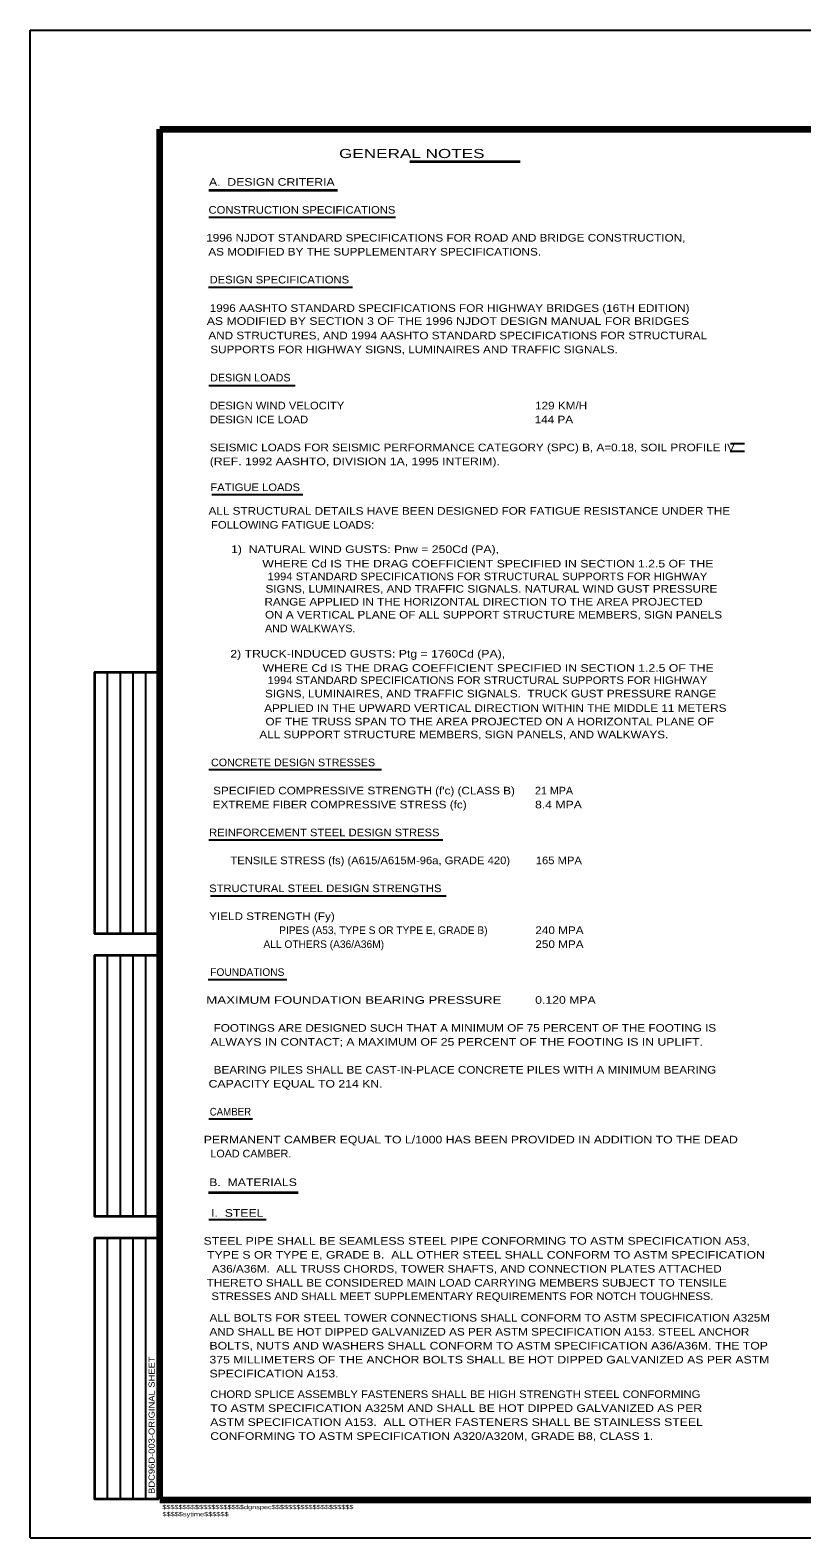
# Model space of a CAD drawing. Extents: x 312601.858 to 312602.699, y 144420.109 to 144420.704.
# Drawn here: x 312601.858 to 312602.162, y 144420.109 to 144420.704 of the extents above; entities that cross this region are included whole.
import ezdxf
from ezdxf.enums import TextEntityAlignment as Align

# ---------------------------------------------------------------- set-up
doc = ezdxf.new("R2010")
doc.units = 0
doc.header["$LTSCALE"] = 0.0012
for name, color, linetype, lineweight in [('2', 7, 'Continuous', 25), ('39', 7, 'Continuous', 25), ('60', 7, 'Continuous', 25)]:
    doc.layers.add(name, color=color, linetype=linetype, lineweight=lineweight)

msp = doc.modelspace()

# ---------------------------------------------------------------- linework, layer by layer
at = {"layer": '2', "lineweight": 35}
for p, q in [((312602.0073, 144420.6518), (312602.0507, 144420.6518)), ((312601.9282, 144420.6405), (312601.9788, 144420.6405)), ((312601.928, 144420.2456), (312601.9633, 144420.2456))]:
    msp.add_line(p, q, dxfattribs=at)
at = {"layer": '2'}
for p, q in [((312601.9282, 144420.6298), (312602.0017, 144420.6298)), ((312601.928, 144420.6023), (312601.9847, 144420.6023)), ((312601.9281, 144420.5635), (312601.9622, 144420.5635)), ((312602.1335, 144420.5406), (312602.139, 144420.5406)), ((312602.1334, 144420.5376), (312602.139, 144420.5376)), ((312601.9293, 144420.5205), (312601.9652, 144420.5205)), ((312601.9282, 144420.4122), (312601.9961, 144420.4122)), ((312601.9282, 144420.3845), (312602.0203, 144420.3845)), ((312601.9288, 144420.3625), (312602.0216, 144420.3625)), ((312601.9279, 144420.3295), (312601.9589, 144420.3295)), ((312601.9281, 144420.2746), (312601.9453, 144420.2746)), ((312601.9281, 144420.2349), (312601.9507, 144420.2349))]:
    msp.add_line(p, q, dxfattribs=at)
at = {"layer": '39'}
for p, q in [((312601.8578, 144420.7035), (312602.6988, 144420.7035)), ((312601.8578, 144420.1095), (312601.8578, 144420.7035)), ((312601.8578, 144420.1095), (312602.6988, 144420.1095))]:
    msp.add_line(p, q, dxfattribs=at)
at = {"layer": '39', "lineweight": 158}
for p, q in [((312601.9088, 144420.6645), (312602.6838, 144420.6645)), ((312601.9088, 144420.1247), (312601.9088, 144420.6645)), ((312601.9088, 144420.1245), (312602.6838, 144420.1245))]:
    msp.add_line(p, q, dxfattribs=at)
at = {"layer": '60'}
for p, q in [((312601.8883, 144420.3475), (312601.8883, 144420.4505)), ((312601.8933, 144420.3475), (312601.8933, 144420.4505)), ((312601.8983, 144420.3475), (312601.8983, 144420.4505)), ((312601.9034, 144420.3475), (312601.9034, 144420.4505)), ((312601.8883, 144420.2361), (312601.8883, 144420.3391)), ((312601.8933, 144420.2361), (312601.8933, 144420.3391)), ((312601.8983, 144420.2361), (312601.8983, 144420.3391)), ((312601.9034, 144420.2361), (312601.9034, 144420.3391)), ((312601.8883, 144420.1247), (312601.8883, 144420.2277)), ((312601.8933, 144420.1247), (312601.8933, 144420.2277)), ((312601.8983, 144420.1247), (312601.8983, 144420.2277)), ((312601.9034, 144420.1247), (312601.9034, 144420.2277))]:
    msp.add_line(p, q, dxfattribs=at)
at = {"layer": '60', "lineweight": 35}
for points in [[(312601.9084, 144420.3475), (312601.8833, 144420.3475), (312601.8833, 144420.4505), (312601.9084, 144420.4505)], [(312601.9084, 144420.2361), (312601.8833, 144420.2361), (312601.8833, 144420.3391), (312601.9084, 144420.3391)], [(312601.9084, 144420.1247), (312601.8833, 144420.1247), (312601.8833, 144420.2277), (312601.9084, 144420.2277)]]:
    msp.add_lwpolyline(points, dxfattribs=at)

# ---------------------------------------------------------------- texts
at = {"layer": '2'}
for s, height, width, p in [('                         GENERAL NOTES', 0.0036, 1.4, (312601.98465, 144420.6531)), ('A.  DESIGN CRITERIA', 0.003, 1.2, (312601.95295, 144420.6422)), ('CONSTRUCTION SPECIFICATIONS', 0.003, 1.1, (312601.9648, 144420.6312)), ('1996 NJDOT STANDARD SPECIFICATIONS FOR ROAD AND BRIDGE CONSTRUCTION,', 0.003, 1.15, (312602.02145, 144420.6202)), ('AS MODIFIED BY THE SUPPLEMENTARY SPECIFICATIONS.', 0.003, 1.15, (312601.99345, 144420.6147)), ('DESIGN SPECIFICATIONS', 0.003, 1.1, (312601.9559, 144420.6037)), ('1996 AASHTO STANDARD SPECIFICATIONS FOR HIGHWAY BRIDGES (16TH EDITION)', 0.003, 1.15, (312602.02295, 144420.5925)), ('AS MODIFIED BY SECTION 3 OF THE 1996 NJDOT DESIGN MANUAL FOR BRIDGES', 0.003, 1.2, (312602.0223, 144420.5874)), ('AND STRUCTURES, AND 1994 AASHTO STANDARD SPECIFICATIONS FOR STRUCTURAL', 0.003, 1.15, (312602.02615, 144420.5817)), ('SUPPORTS FOR HIGHWAY SIGNS, LUMINAIRES AND TRAFFIC SIGNALS.', 0.003, 1.15, (312602.00895, 144420.5762)), ('DESIGN LOADS', 0.003, 1.05, (312601.9445, 144420.5651)), ('129 KM/H', 0.003, 1.15, (312602.06685, 144420.5541)), ('144 PA', 0.003, 1.15, (312602.064, 144420.5486)), ('FATIGUE LOADS', 0.003, 1.1, (312601.9464, 144420.5219)), ('ALL STRUCTURAL DETAILS HAVE BEEN DESIGNED FOR FATIGUE RESISTANCE UNDER THE', 0.003, 1.15, (312602.0307, 144420.5126)), ('FOLLOWING FATIGUE LOADS:', 0.003, 1.1, (312601.96115, 144420.5071)), ('1)  NATURAL WIND GUSTS: Pnw = 250Cd (PA),', 0.003, 1.2, (312601.98965, 144420.4975)), ('WHERE Cd IS THE DRAG COEFFICIENT SPECIFIED IN SECTION 1.2.5 OF THE', 0.003, 1.2, (312602.038, 144420.4918)), ('1994 STANDARD SPECIFICATIONS FOR STRUCTURAL SUPPORTS FOR HIGHWAY', 0.003, 1.1, (312602.03785, 144420.4868)), ('RANGE APPLIED IN THE HORIZONTAL DIRECTION TO THE AREA PROJECTED', 0.003, 1.15, (312602.0363, 144420.4768)), ('SIGNS, LUMINAIRES, AND TRAFFIC SIGNALS. NATURAL WIND GUST PRESSURE', 0.003, 1.15, (312602.0394, 144420.4819)), ('ON A VERTICAL PLANE OF ALL SUPPORT STRUCTURE MEMBERS, SIGN PANELS', 0.003, 1.15, (312602.04025, 144420.4717)), ('AND WALKWAYS.', 0.003, 1.05, (312601.96805, 144420.4663)), ('2) TRUCK-INDUCED GUSTS: Ptg = 1760Cd (PA),', 0.003, 1.2, (312601.9907, 144420.4563)), ('WHERE Cd IS THE DRAG COEFFICIENT SPECIFIED IN SECTION 1.2.5 OF THE', 0.003, 1.2, (312602.0381, 144420.4507)), ('SIGNS, LUMINAIRES, AND TRAFFIC SIGNALS.  TRUCK GUST PRESSURE RANGE', 0.003, 1.15, (312602.0391, 144420.4406)), ('1994 STANDARD SPECIFICATIONS FOR STRUCTURAL SUPPORTS FOR HIGHWAY', 0.003, 1.1, (312602.03785, 144420.4459)), ('APPLIED IN THE UPWARD VERTICAL DIRECTION WITHIN THE MIDDLE 11 METERS', 0.003, 1.15, (312602.04095, 144420.4349)), ('OF THE TRUSS SPAN TO THE AREA PROJECTED ON A HORIZONTAL PLANE OF', 0.003, 1.15, (312602.03875, 144420.4296)), ('ALL SUPPORT STRUCTURE MEMBERS, SIGN PANELS, AND WALKWAYS.', 0.003, 1.15, (312602.02855, 144420.4245)), ('CONCRETE DESIGN STRESSES', 0.003, 1.05, (312601.9613, 144420.4135)), ("SPECIFIED COMPRESSIVE STRENGTH (f'c) (CLASS B)          ", 0.003, 1.15, (312601.99565, 144420.4024)), ('21 MPA', 0.003, 1.05, (312602.06405, 144420.4024)), ('EXTREME FIBER COMPRESSIVE STRESS (fc)             ', 0.003, 1.15, (312601.988, 144420.3969)), ('8.4 MPA', 0.003, 1.2, (312602.0658, 144420.3969)), ('REINFORCEMENT STEEL DESIGN STRESS', 0.003, 1.1, (312601.9736, 144420.3859)), ('TENSILE STRESS (fs) (A615/A615M-96a, GRADE 420)                        ', 0.003, 1.1, (312602.0064, 144420.3749)), ('165 MPA', 0.003, 1.1, (312602.06595, 144420.3749)), ('STRUCTURAL STEEL DESIGN STRENGTHS', 0.003, 1.1, (312601.974, 144420.3639)), ('YIELD STRENGTH (Fy)', 0.003, 1.15, (312601.953, 144420.3529)), ('240 MPA', 0.003, 1.15, (312602.0662, 144420.3474)), ('250 MPA', 0.003, 1.15, (312602.0662, 144420.3419)), ('MAXIMUM FOUNDATION BEARING PRESSURE             ', 0.003, 1.3, (312601.99465, 144420.3199)), ('0.120 MPA', 0.003, 1.2, (312602.06855, 144420.3199)), ('FOOTINGS ARE DESIGNED SUCH THAT A MINIMUM OF 75 PERCENT OF THE FOOTING IS', 0.003, 1.15, (312602.02895, 144420.3089)), ('ALWAYS IN CONTACT; A MAXIMUM OF 25 PERCENT OF THE FOOTING IS IN UPLIFT.', 0.003, 1.2, (312602.02575, 144420.3034)), ('BEARING PILES SHALL BE CAST-IN-PLACE CONCRETE PILES WITH A MINIMUM BEARING', 0.003, 1.15, (312602.029, 144420.2924)), ('CAPACITY EQUAL TO 214 KN.', 0.003, 1.2, (312601.9623, 144420.2869)), ('CAMBER', 0.003, 0.95, (312601.93665, 144420.2759)), ('PERMANENT CAMBER EQUAL TO L/1000 HAS BEEN PROVIDED IN ADDITION TO THE DEAD', 0.003, 1.2, (312602.0313, 144420.2649)), ('LOAD CAMBER.', 0.003, 1.05, (312601.9447, 144420.2594)), ('B.  MATERIALS', 0.003, 1.2, (312601.94555, 144420.2481)), ('I.  STEEL', 0.003, 1.2, (312601.93935, 144420.236)), ('STEEL PIPE SHALL BE SEAMLESS STEEL PIPE CONFORMING TO ASTM SPECIFICATION A53,', 0.003, 1.2, (312602.0336, 144420.225)), ('TYPE S OR TYPE E, GRADE B.  ALL OTHER STEEL SHALL CONFORM TO ASTM SPECIFICATION', 0.003, 1.2, (312602.03725, 144420.2195)), ('A36/A36M.  ALL TRUSS CHORDS, TOWER SHAFTS, AND CONNECTION PLATES ATTACHED', 0.003, 1.15, (312602.0297, 144420.214)), ('THERETO SHALL BE CONSIDERED MAIN LOAD CARRYING MEMBERS SUBJECT TO TENSILE', 0.003, 1.15, (312602.0297, 144420.2085)), ('STRESSES AND SHALL MEET SUPPLEMENTARY REQUIREMENTS FOR NOTCH TOUGHNESS.', 0.003, 1.1, (312602.028, 144420.2032))]:
    msp.add_text(s, height=height, dxfattribs=dict(at, width=width)).set_placement(p, align=Align.CENTER)
for s, height, width, p in [('DESIGN WIND VELOCITY', 0.003, 1.1, (312601.9285, 144420.5541)), ('DESIGN ICE LOAD', 0.003, 1.1, (312601.9285, 144420.5486)), ('SEISMIC LOADS FOR SEISMIC PERFORMANCE CATEGORY (SPC) B, A=0.18, SOIL PROFILE IV', 0.003, 1.15, (312601.9285, 144420.5376)), ('(REF. 1992 AASHTO, DIVISION 1A, 1995 INTERIM).', 0.003, 1.2, (312601.9285, 144420.5321)), ('ALL BOLTS FOR STEEL TOWER CONNECTIONS SHALL CONFORM TO ASTM SPECIFICATION A325M', 0.003, 1.15, (312601.9284, 144420.1947)), ('AND SHALL BE HOT DIPPED GALVANIZED AS PER ASTM SPECIFICATION A153. STEEL ANCHOR', 0.003, 1.15, (312601.9284, 144420.1892)), ('BOLTS, NUTS AND WASHERS SHALL CONFORM TO ASTM SPECIFICATION A36/A36M. THE TOP', 0.003, 1.2, (312601.9284, 144420.1837)), ('375 MILLIMETERS OF THE ANCHOR BOLTS SHALL BE HOT DIPPED GALVANIZED AS PER ASTM', 0.003, 1.2, (312601.9284, 144420.1782)), ('SPECIFICATION A153.  ', 0.003, 1.2, (312601.9284, 144420.1727)), ('CHORD SPLICE ASSEMBLY FASTENERS SHALL BE HIGH STRENGTH STEEL CONFORMING', 0.003, 1.1, (312601.9287, 144420.1646)), ('TO ASTM SPECIFICATION A325M AND SHALL BE HOT DIPPED GALVANIZED AS PER', 0.003, 1.2, (312601.9287, 144420.1591)), ('ASTM SPECIFICATION A153.  ALL OTHER FASTENERS SHALL BE STAINLESS STEEL', 0.003, 1.2, (312601.9287, 144420.1536)), ('CONFORMING TO ASTM SPECIFICATION A320/A320M, GRADE B8, CLASS 1.', 0.003, 1.2, (312601.9287, 144420.1481)), ('$$$$$$$$$$$$$$$$$$$$dgnspec$$$$$$$$$$$$$$$$$$$$', 0.001664, 1.3, (312601.9098, 144420.1208)), ('$$$$$sytime$$$$$$', 0.001664, 1.3, (312601.9099, 144420.118))]:
    msp.add_text(s, height=height, dxfattribs=dict(at, width=width)).set_placement(p)
for s, p in [('     PIPES (A53, TYPE S OR TYPE E, GRADE B)                                      ', (312602.01525, 144420.3474)), ('     ALL OTHERS (A36/A36M)                                ', (312601.98845, 144420.3419)), ('FOUNDATIONS', (312601.9433, 144420.3309))]:
    msp.add_text(s, height=0.003, dxfattribs=at).set_placement(p, align=Align.CENTER)
at = {"layer": '2', "width": 1.15}
msp.add_text('BDC96D-003-ORIGINAL SHEET', height=0.0024, rotation=90, dxfattribs=at).set_placement((312601.9068, 144420.1539), align=Align.CENTER)

doc.saveas('drawing.dxf')
